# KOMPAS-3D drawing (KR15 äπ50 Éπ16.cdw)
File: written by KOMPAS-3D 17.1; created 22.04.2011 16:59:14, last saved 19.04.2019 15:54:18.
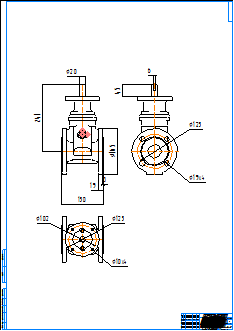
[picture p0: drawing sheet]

Title block, sheet 1: name: KR15 Ду50 Ру16; material: Внимание! Данный продукт является объектом авторского права ООО «Торговый Дом АДЛ». / Запрещается изменение, копирование, распространение / (в том числе путем копирования на другие сайты и ресурсы в Интернете) / или любое иное использование информации и объектов без предварительного / согласия правообладателя (ООО «Торговый Дом АДЛ»).; scale: 1:1; sheets: 1; organisation: ООО "Торговый дом АДЛ"; sheet format: A0; stored path: \\adlc.lan\data\АДЛ_ПКД\3D-модели\ADL production\Клиновые задвижки серии KR ГРАНАР\Клиновые задвижки KR15\С голым штоком\KOMPAS 2D\KR15 Ду50 Ру16.cdw

Views: Спереди 4, Проекционный вид 5, Проекционный вид 6
Dimensions and other numbers on the sheet: 150; 19; 3; 165; 241; 20; 125; 102; 10; 45; 6; 1:1; 1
